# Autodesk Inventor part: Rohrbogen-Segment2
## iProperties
Created: 2006-10
Part Number: Rohrbogen-Segment2
Cost Center: 1,69 kg
Material: 1.4301 (X5CrNi18 10)
Document SubType Name: Sheet Metal
Designer: grote
Authority: 210865,8 mm^3
Manufacturer: Standard
Standards Organization: Custom
Objekthöhe: 10,000 mm
SaveDate: 2006-10-11
SaveTime: 08:21
FileName: Rohrbogen-Segment2
TotalMass: 1,69 kg
TotalVolume: 210865,8 mm^3
SM_Thickness: 10 mm
SM_Style: NIRO-V80(t =4-10 mm)
SM_Extents: 205,013 mm x 164,022 mm
SM_Square: 33627 mm²
SM_Extents_Width: 205,013 mm
SM_Extents_Length: 164,022 mm
Author: grote
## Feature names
1. Trennen1
2. Trennen2
3. Abgeleiteter Körper1 [Tagging]
4. ExtrusionAbwicklung1
